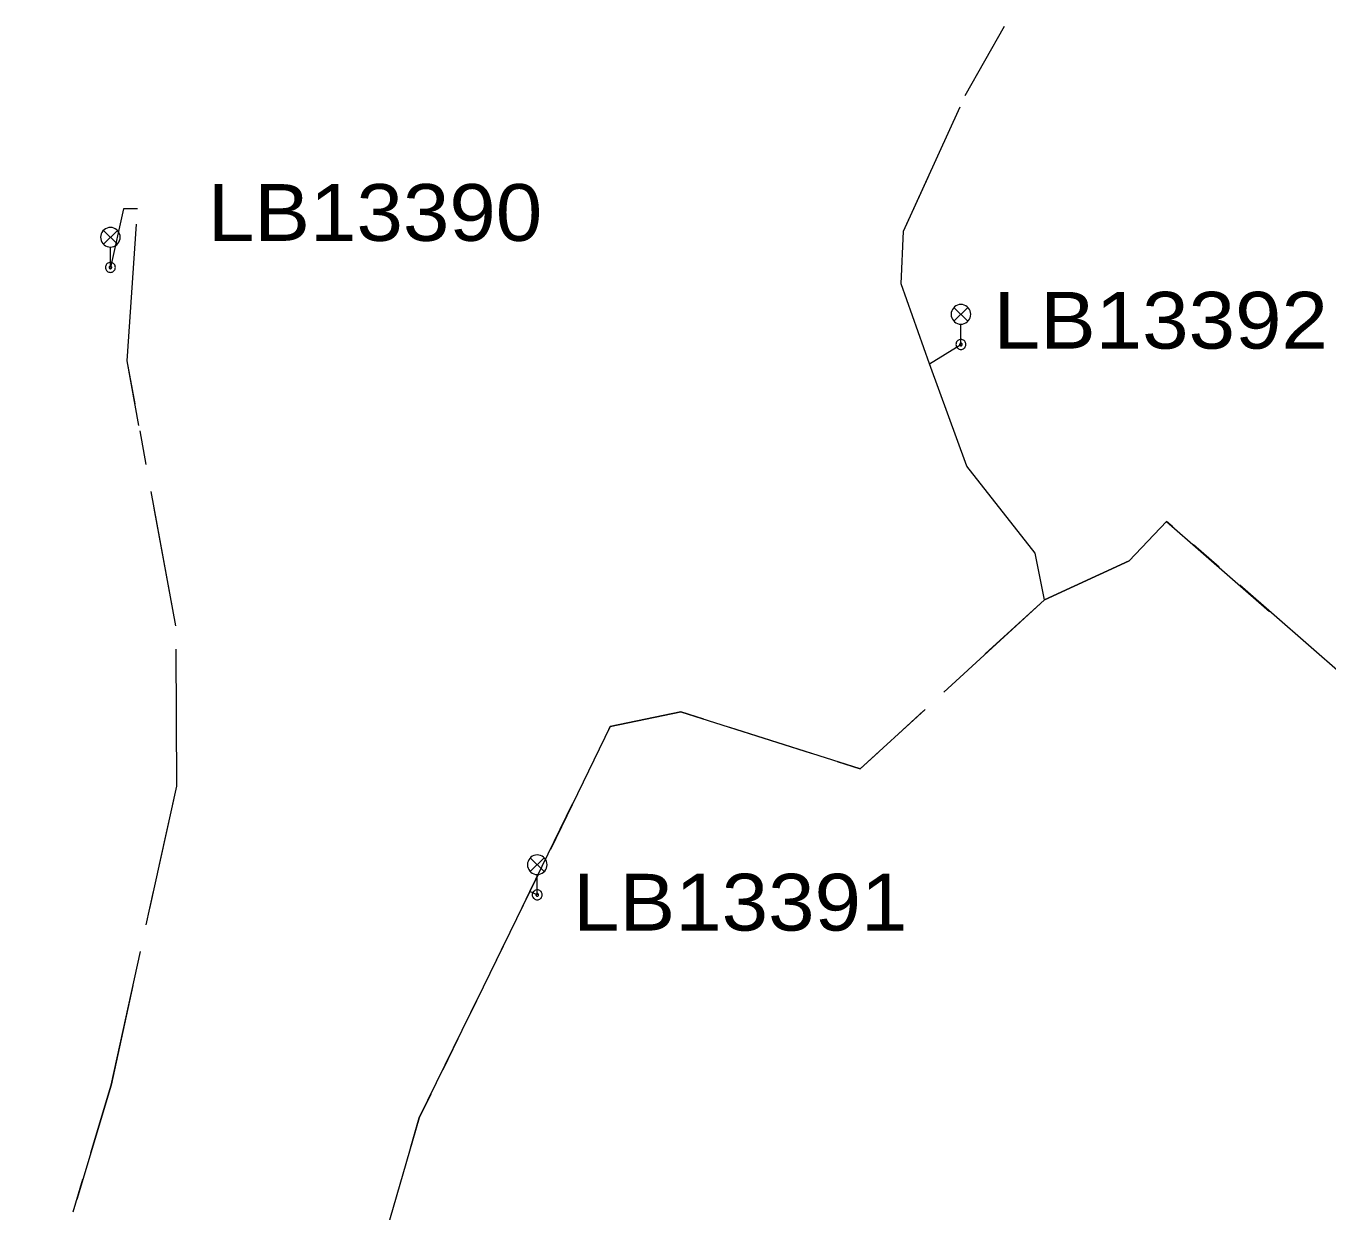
# Model space of a CAD drawing. Extents: x -688049 to -687261, y -973611 to -973038.
# Drawn here: x -687572.31 to -687522.62, y -973099.72 to -973054.47 of the extents above; entities that cross this region are included whole.
import ezdxf

# ---------------------------------------------------------------- set-up
doc = ezdxf.new("R2010")
doc.units = 0
doc.header["$LTSCALE"] = 0.87
doc.linetypes.add('LONG_DASH_SHORT_DASH', pattern=[9.9, 6, -1.2, 1.5, -1.2])
doc.layers.add('1', color=7, linetype='Continuous', lineweight=13)

msp = doc.modelspace()

# ---------------------------------------------------------------- linework, layer by layer
at = {"layer": '1'}
for p, q in [((-687569.355, -973062.265), (-687568.825, -973062.795)), ((-687569.355, -973062.795), (-687568.825, -973062.265)), ((-687569.09, -973063.68), (-687569.09, -973062.905)), ((-687536.895, -973065.205), (-687536.365, -973065.735)), ((-687536.895, -973065.735), (-687536.365, -973065.205)), ((-687536.63, -973066.62), (-687536.63, -973065.845)), ((-687553.065, -973086.205), (-687552.535, -973086.735)), ((-687553.065, -973086.735), (-687552.535, -973086.205)), ((-687552.8, -973087.62), (-687552.8, -973086.845))]:
    msp.add_line(p, q, dxfattribs=at)
at = {"layer": '1', "linetype": 'LONG_DASH_SHORT_DASH'}
for p, q in [((-687537.83, -973067.36), (-687536.63, -973066.62)), ((-687537.83, -973067.36), (-687536.63, -973066.62)), ((-687537.83, -973067.36), (-687536.63, -973066.62)), ((-687537.83, -973067.36), (-687536.63, -973066.62)), ((-687537.83, -973067.36), (-687536.63, -973066.62)), ((-687537.83, -973067.36), (-687536.63, -973066.62)), ((-687537.83, -973067.36), (-687536.63, -973066.62)), ((-687535.7, -973078.43), (-687533.44, -973076.36)), ((-687535.7, -973078.43), (-687533.44, -973076.36)), ((-687535.7, -973078.43), (-687533.44, -973076.36)), ((-687535.7, -973078.43), (-687533.44, -973076.36)), ((-687553.08, -973087.49), (-687551.45, -973084.15)), ((-687553.08, -973087.49), (-687551.45, -973084.15)), ((-687553.08, -973087.49), (-687551.45, -973084.15)), ((-687552.8, -973087.62), (-687553.08, -973087.49)), ((-687552.8, -973087.62), (-687553.08, -973087.49)), ((-687552.8, -973087.62), (-687553.08, -973087.49)), ((-687552.8, -973087.62), (-687553.08, -973087.49))]:
    msp.add_line(p, q, dxfattribs=at)
for points in [[(-687537.83, -973067.36), (-687538.91, -973064.3), (-687538.82, -973062.3), (-687536.47, -973057.12), (-687534.97, -973054.47)], [(-687537.83, -973067.36), (-687538.91, -973064.3), (-687538.82, -973062.3), (-687536.47, -973057.12), (-687534.97, -973054.47)], [(-687537.83, -973067.36), (-687538.91, -973064.3), (-687538.82, -973062.3), (-687536.47, -973057.12), (-687534.97, -973054.47)], [(-687537.83, -973067.36), (-687538.91, -973064.3), (-687538.82, -973062.3), (-687536.47, -973057.12), (-687534.97, -973054.47)], [(-687537.83, -973067.36), (-687538.91, -973064.3), (-687538.82, -973062.3), (-687537.88, -973060.23)], [(-687537.83, -973067.36), (-687538.91, -973064.3), (-687538.82, -973062.3), (-687537.88, -973060.23)], [(-687537.83, -973067.36), (-687538.91, -973064.3), (-687538.82, -973062.3), (-687537.88, -973060.23)], [(-687537.83, -973067.36), (-687538.91, -973064.3), (-687538.82, -973062.3), (-687537.88, -973060.23)], [(-687572.31, -973105.72), (-687569.06, -973094.88), (-687566.56, -973083.47), (-687566.59, -973077.36), (-687568.45, -973067.24), (-687568.05, -973061.45)], [(-687572.31, -973105.72), (-687569.06, -973094.88), (-687566.56, -973083.47), (-687566.59, -973077.36), (-687568.45, -973067.24), (-687568.05, -973061.45)], [(-687572.31, -973105.72), (-687569.06, -973094.88), (-687566.56, -973083.47), (-687566.59, -973077.36), (-687568.45, -973067.24), (-687568.05, -973061.45)], [(-687572.31, -973105.72), (-687569.06, -973094.88), (-687566.56, -973083.47), (-687566.59, -973077.36), (-687568.45, -973067.24), (-687568.05, -973061.45)], [(-687568.05, -973061.45), (-687568.59, -973061.44), (-687569.09, -973063.68)], [(-687568.05, -973061.45), (-687568.59, -973061.44), (-687569.09, -973063.68)], [(-687568.05, -973061.45), (-687568.59, -973061.44), (-687569.09, -973063.68)], [(-687568.05, -973061.45), (-687568.59, -973061.44), (-687569.09, -973063.68)], [(-687568.05, -973061.45), (-687568.59, -973061.44), (-687569.09, -973063.68)], [(-687568.05, -973061.45), (-687568.59, -973061.44), (-687569.09, -973063.68)], [(-687568.05, -973061.45), (-687568.59, -973061.44), (-687569.09, -973063.68)], [(-687568.05, -973061.45), (-687568.59, -973061.44), (-687569.09, -973063.68)], [(-687568, -973069.71), (-687568.45, -973067.24), (-687568.05, -973061.45)], [(-687568, -973069.71), (-687568.45, -973067.24), (-687568.05, -973061.45)], [(-687568, -973069.71), (-687568.45, -973067.24), (-687568.05, -973061.45)], [(-687568, -973069.71), (-687568.45, -973067.24), (-687568.05, -973061.45)], [(-687533.44, -973076.36), (-687533.8, -973074.58), (-687536.4, -973071.26), (-687537.83, -973067.36), (-687536.63, -973066.62)], [(-687533.44, -973076.36), (-687533.8, -973074.58), (-687536.4, -973071.26), (-687537.83, -973067.36)], [(-687533.44, -973076.36), (-687533.8, -973074.58), (-687536.4, -973071.26), (-687537.83, -973067.36)], [(-687533.44, -973076.36), (-687533.8, -973074.58), (-687536.4, -973071.26), (-687537.83, -973067.36)], [(-687533.44, -973076.36), (-687533.8, -973074.58), (-687536.4, -973071.26), (-687537.83, -973067.36)], [(-687533.44, -973076.36), (-687533.8, -973074.58), (-687536.4, -973071.26), (-687537.83, -973067.36)], [(-687533.44, -973076.36), (-687533.8, -973074.58), (-687536.4, -973071.26), (-687537.83, -973067.36)], [(-687533.44, -973076.36), (-687533.8, -973074.58), (-687536.4, -973071.26), (-687537.83, -973067.36)], [(-687567.58, -973088.14), (-687566.56, -973083.47), (-687566.59, -973077.36), (-687567.42, -973072.87)], [(-687567.58, -973088.14), (-687566.56, -973083.47), (-687566.59, -973077.36), (-687567.42, -973072.87)], [(-687567.58, -973088.14), (-687566.56, -973083.47), (-687566.59, -973077.36), (-687567.42, -973072.87)], [(-687567.58, -973088.14), (-687566.56, -973083.47), (-687566.59, -973077.36), (-687567.42, -973072.87)], [(-687499.78, -973111.37), (-687498.29, -973106.94), (-687504.37, -973096.01), (-687522.05, -973079.24), (-687528.78, -973073.37), (-687530.21, -973074.88), (-687533.44, -973076.36)], [(-687499.78, -973111.37), (-687498.29, -973106.94), (-687504.37, -973096.01), (-687522.05, -973079.24), (-687528.78, -973073.37), (-687530.21, -973074.88), (-687533.44, -973076.36)], [(-687499.78, -973111.37), (-687498.29, -973106.94), (-687504.37, -973096.01), (-687522.05, -973079.24), (-687528.78, -973073.37), (-687530.21, -973074.88), (-687533.44, -973076.36)], [(-687499.78, -973111.37), (-687498.29, -973106.94), (-687504.37, -973096.01), (-687522.05, -973079.24), (-687528.78, -973073.37), (-687530.21, -973074.88), (-687533.44, -973076.36)], [(-687533.44, -973076.36), (-687530.21, -973074.88), (-687528.78, -973073.37), (-687524.67, -973076.96)], [(-687533.44, -973076.36), (-687530.21, -973074.88), (-687528.78, -973073.37), (-687524.67, -973076.96)], [(-687533.44, -973076.36), (-687530.21, -973074.88), (-687528.78, -973073.37), (-687524.67, -973076.96)], [(-687533.44, -973076.36), (-687530.21, -973074.88), (-687528.78, -973073.37), (-687524.67, -973076.96)], [(-687533.44, -973076.36), (-687540.47, -973082.81), (-687547.32, -973080.64), (-687550.01, -973081.2), (-687553.08, -973087.49)], [(-687533.44, -973076.36), (-687540.47, -973082.81), (-687547.32, -973080.64), (-687550.01, -973081.2), (-687553.08, -973087.49)], [(-687533.44, -973076.36), (-687540.47, -973082.81), (-687547.32, -973080.64), (-687550.01, -973081.2), (-687553.08, -973087.49)], [(-687533.44, -973076.36), (-687540.47, -973082.81), (-687547.32, -973080.64), (-687550.01, -973081.2), (-687553.08, -973087.49), (-687551.45, -973084.15)], [(-687550.12, -973081.43), (-687550.01, -973081.2), (-687547.32, -973080.64), (-687540.47, -973082.81), (-687538, -973080.55)], [(-687550.12, -973081.43), (-687550.01, -973081.2), (-687547.32, -973080.64), (-687540.47, -973082.81), (-687538, -973080.55)], [(-687550.12, -973081.43), (-687550.01, -973081.2), (-687547.32, -973080.64), (-687540.47, -973082.81), (-687538, -973080.55)], [(-687550.12, -973081.43), (-687550.01, -973081.2), (-687547.32, -973080.64), (-687540.47, -973082.81), (-687538, -973080.55)], [(-687553.08, -973087.49), (-687557.3, -973096.13), (-687561.28, -973109.72)], [(-687553.08, -973087.49), (-687557.3, -973096.13), (-687561.28, -973109.72)], [(-687553.08, -973087.49), (-687557.3, -973096.13), (-687561.28, -973109.72), (-687558.49, -973100.2)], [(-687553.08, -973087.49), (-687557.3, -973096.13), (-687561.28, -973109.72)], [(-687557.64, -973097.28), (-687557.3, -973096.13), (-687553.08, -973087.49)], [(-687557.64, -973097.28), (-687557.3, -973096.13), (-687553.08, -973087.49)], [(-687557.64, -973097.28), (-687557.3, -973096.13), (-687553.08, -973087.49)], [(-687557.64, -973097.28), (-687557.3, -973096.13), (-687553.08, -973087.49)], [(-687568.23, -973091.08), (-687569.06, -973094.88), (-687570.37, -973099.24)], [(-687568.23, -973091.08), (-687569.06, -973094.88), (-687570.37, -973099.24)], [(-687568.23, -973091.08), (-687569.06, -973094.88), (-687570.37, -973099.24)], [(-687568.23, -973091.08), (-687569.06, -973094.88), (-687570.37, -973099.24)]]:
    msp.add_lwpolyline(points, dxfattribs=at)
at = {"layer": '1'}
for points in [[(-687568.715, -973062.53), (-687568.721, -973062.465), (-687568.738, -973062.402), (-687568.765, -973062.342), (-687568.803, -973062.289), (-687568.849, -973062.243), (-687568.902, -973062.205), (-687568.962, -973062.178), (-687569.025, -973062.161), (-687569.09, -973062.155), (-687569.155, -973062.161), (-687569.218, -973062.178), (-687569.278, -973062.205), (-687569.331, -973062.243), (-687569.377, -973062.289), (-687569.415, -973062.342), (-687569.442, -973062.402), (-687569.459, -973062.465), (-687569.465, -973062.53), (-687569.459, -973062.595), (-687569.442, -973062.658), (-687569.415, -973062.718), (-687569.377, -973062.771), (-687569.331, -973062.817), (-687569.278, -973062.855), (-687569.218, -973062.882), (-687569.155, -973062.899), (-687569.09, -973062.905), (-687569.025, -973062.899), (-687568.962, -973062.882), (-687568.902, -973062.855), (-687568.849, -973062.817), (-687568.803, -973062.771), (-687568.765, -973062.718), (-687568.738, -973062.658), (-687568.721, -973062.595)], [(-687568.9, -973063.68), (-687568.903, -973063.647), (-687568.911, -973063.615), (-687568.925, -973063.585), (-687568.944, -973063.558), (-687568.968, -973063.534), (-687568.995, -973063.515), (-687569.025, -973063.501), (-687569.057, -973063.493), (-687569.09, -973063.49), (-687569.123, -973063.493), (-687569.155, -973063.501), (-687569.185, -973063.515), (-687569.212, -973063.534), (-687569.236, -973063.558), (-687569.255, -973063.585), (-687569.269, -973063.615), (-687569.277, -973063.647), (-687569.28, -973063.68), (-687569.277, -973063.713), (-687569.269, -973063.745), (-687569.255, -973063.775), (-687569.236, -973063.802), (-687569.212, -973063.826), (-687569.185, -973063.845), (-687569.155, -973063.859), (-687569.123, -973063.867), (-687569.09, -973063.87), (-687569.057, -973063.867), (-687569.025, -973063.859), (-687568.995, -973063.845), (-687568.968, -973063.826), (-687568.944, -973063.802), (-687568.925, -973063.775), (-687568.911, -973063.745), (-687568.903, -973063.713)], [(-687569.04, -973063.68), (-687569.041, -973063.671), (-687569.043, -973063.663), (-687569.047, -973063.655), (-687569.052, -973063.648), (-687569.058, -973063.642), (-687569.065, -973063.637), (-687569.073, -973063.633), (-687569.081, -973063.631), (-687569.09, -973063.63), (-687569.099, -973063.631), (-687569.107, -973063.633), (-687569.115, -973063.637), (-687569.122, -973063.642), (-687569.128, -973063.648), (-687569.133, -973063.655), (-687569.137, -973063.663), (-687569.139, -973063.671), (-687569.14, -973063.68), (-687569.139, -973063.689), (-687569.137, -973063.697), (-687569.133, -973063.705), (-687569.128, -973063.712), (-687569.122, -973063.718), (-687569.115, -973063.723), (-687569.107, -973063.727), (-687569.099, -973063.729), (-687569.09, -973063.73), (-687569.081, -973063.729), (-687569.073, -973063.727), (-687569.065, -973063.723), (-687569.058, -973063.718), (-687569.052, -973063.712), (-687569.047, -973063.705), (-687569.043, -973063.697), (-687569.041, -973063.689)], [(-687536.255, -973065.47), (-687536.261, -973065.405), (-687536.278, -973065.342), (-687536.305, -973065.283), (-687536.343, -973065.229), (-687536.389, -973065.183), (-687536.442, -973065.145), (-687536.502, -973065.118), (-687536.565, -973065.101), (-687536.63, -973065.095), (-687536.695, -973065.101), (-687536.758, -973065.118), (-687536.818, -973065.145), (-687536.871, -973065.183), (-687536.917, -973065.229), (-687536.955, -973065.283), (-687536.982, -973065.342), (-687536.999, -973065.405), (-687537.005, -973065.47), (-687536.999, -973065.535), (-687536.982, -973065.598), (-687536.955, -973065.658), (-687536.917, -973065.711), (-687536.871, -973065.757), (-687536.818, -973065.795), (-687536.758, -973065.822), (-687536.695, -973065.839), (-687536.63, -973065.845), (-687536.565, -973065.839), (-687536.502, -973065.822), (-687536.442, -973065.795), (-687536.389, -973065.757), (-687536.343, -973065.711), (-687536.305, -973065.658), (-687536.278, -973065.598), (-687536.261, -973065.535)], [(-687536.44, -973066.62), (-687536.443, -973066.587), (-687536.451, -973066.555), (-687536.465, -973066.525), (-687536.484, -973066.498), (-687536.508, -973066.474), (-687536.535, -973066.455), (-687536.565, -973066.441), (-687536.597, -973066.433), (-687536.63, -973066.43), (-687536.663, -973066.433), (-687536.695, -973066.441), (-687536.725, -973066.455), (-687536.752, -973066.474), (-687536.776, -973066.498), (-687536.795, -973066.525), (-687536.809, -973066.555), (-687536.817, -973066.587), (-687536.82, -973066.62), (-687536.817, -973066.653), (-687536.809, -973066.685), (-687536.795, -973066.715), (-687536.776, -973066.742), (-687536.752, -973066.766), (-687536.725, -973066.785), (-687536.695, -973066.799), (-687536.663, -973066.807), (-687536.63, -973066.81), (-687536.597, -973066.807), (-687536.565, -973066.799), (-687536.535, -973066.785), (-687536.508, -973066.766), (-687536.484, -973066.742), (-687536.465, -973066.715), (-687536.451, -973066.685), (-687536.443, -973066.653)], [(-687536.58, -973066.62), (-687536.581, -973066.611), (-687536.583, -973066.603), (-687536.587, -973066.595), (-687536.592, -973066.588), (-687536.598, -973066.582), (-687536.605, -973066.577), (-687536.613, -973066.573), (-687536.621, -973066.571), (-687536.63, -973066.57), (-687536.639, -973066.571), (-687536.647, -973066.573), (-687536.655, -973066.577), (-687536.662, -973066.582), (-687536.668, -973066.588), (-687536.673, -973066.595), (-687536.677, -973066.603), (-687536.679, -973066.611), (-687536.68, -973066.62), (-687536.679, -973066.629), (-687536.677, -973066.637), (-687536.673, -973066.645), (-687536.668, -973066.652), (-687536.662, -973066.658), (-687536.655, -973066.663), (-687536.647, -973066.667), (-687536.639, -973066.669), (-687536.63, -973066.67), (-687536.621, -973066.669), (-687536.613, -973066.667), (-687536.605, -973066.663), (-687536.598, -973066.658), (-687536.592, -973066.652), (-687536.587, -973066.645), (-687536.583, -973066.637), (-687536.581, -973066.629)], [(-687552.425, -973086.47), (-687552.431, -973086.405), (-687552.448, -973086.342), (-687552.475, -973086.283), (-687552.513, -973086.229), (-687552.559, -973086.183), (-687552.612, -973086.145), (-687552.672, -973086.118), (-687552.735, -973086.101), (-687552.8, -973086.095), (-687552.865, -973086.101), (-687552.928, -973086.118), (-687552.988, -973086.145), (-687553.041, -973086.183), (-687553.087, -973086.229), (-687553.125, -973086.283), (-687553.152, -973086.342), (-687553.169, -973086.405), (-687553.175, -973086.47), (-687553.169, -973086.535), (-687553.152, -973086.598), (-687553.125, -973086.658), (-687553.087, -973086.711), (-687553.041, -973086.757), (-687552.988, -973086.795), (-687552.928, -973086.822), (-687552.865, -973086.839), (-687552.8, -973086.845), (-687552.735, -973086.839), (-687552.672, -973086.822), (-687552.612, -973086.795), (-687552.559, -973086.757), (-687552.513, -973086.711), (-687552.475, -973086.658), (-687552.448, -973086.598), (-687552.431, -973086.535)], [(-687552.61, -973087.62), (-687552.613, -973087.587), (-687552.621, -973087.555), (-687552.635, -973087.525), (-687552.654, -973087.498), (-687552.678, -973087.474), (-687552.705, -973087.455), (-687552.735, -973087.441), (-687552.767, -973087.433), (-687552.8, -973087.43), (-687552.833, -973087.433), (-687552.865, -973087.441), (-687552.895, -973087.455), (-687552.922, -973087.474), (-687552.946, -973087.498), (-687552.965, -973087.525), (-687552.979, -973087.555), (-687552.987, -973087.587), (-687552.99, -973087.62), (-687552.987, -973087.653), (-687552.979, -973087.685), (-687552.965, -973087.715), (-687552.946, -973087.742), (-687552.922, -973087.766), (-687552.895, -973087.785), (-687552.865, -973087.799), (-687552.833, -973087.807), (-687552.8, -973087.81), (-687552.767, -973087.807), (-687552.735, -973087.799), (-687552.705, -973087.785), (-687552.678, -973087.766), (-687552.654, -973087.742), (-687552.635, -973087.715), (-687552.621, -973087.685), (-687552.613, -973087.653)], [(-687552.75, -973087.62), (-687552.751, -973087.611), (-687552.753, -973087.603), (-687552.757, -973087.595), (-687552.762, -973087.588), (-687552.768, -973087.582), (-687552.775, -973087.577), (-687552.783, -973087.573), (-687552.791, -973087.571), (-687552.8, -973087.57), (-687552.809, -973087.571), (-687552.817, -973087.573), (-687552.825, -973087.577), (-687552.832, -973087.582), (-687552.838, -973087.588), (-687552.843, -973087.595), (-687552.847, -973087.603), (-687552.849, -973087.611), (-687552.85, -973087.62), (-687552.849, -973087.629), (-687552.847, -973087.637), (-687552.843, -973087.645), (-687552.838, -973087.652), (-687552.832, -973087.658), (-687552.825, -973087.663), (-687552.817, -973087.667), (-687552.809, -973087.669), (-687552.8, -973087.67), (-687552.791, -973087.669), (-687552.783, -973087.667), (-687552.775, -973087.663), (-687552.768, -973087.658), (-687552.762, -973087.652), (-687552.757, -973087.645), (-687552.753, -973087.637), (-687552.751, -973087.629)]]:
    msp.add_lwpolyline(points, close=True, dxfattribs=at)

# ---------------------------------------------------------------- texts
at = {"layer": '1', "width": 1.1}
for s, p in [('LB13390', (-687565.371, -973062.667)), ('LB13392', (-687535.384, -973066.78)), ('LB13391', (-687551.433, -973088.984))]:
    msp.add_text(s, height=2.167, dxfattribs=at).set_placement(p)

doc.saveas('drawing.dxf')
